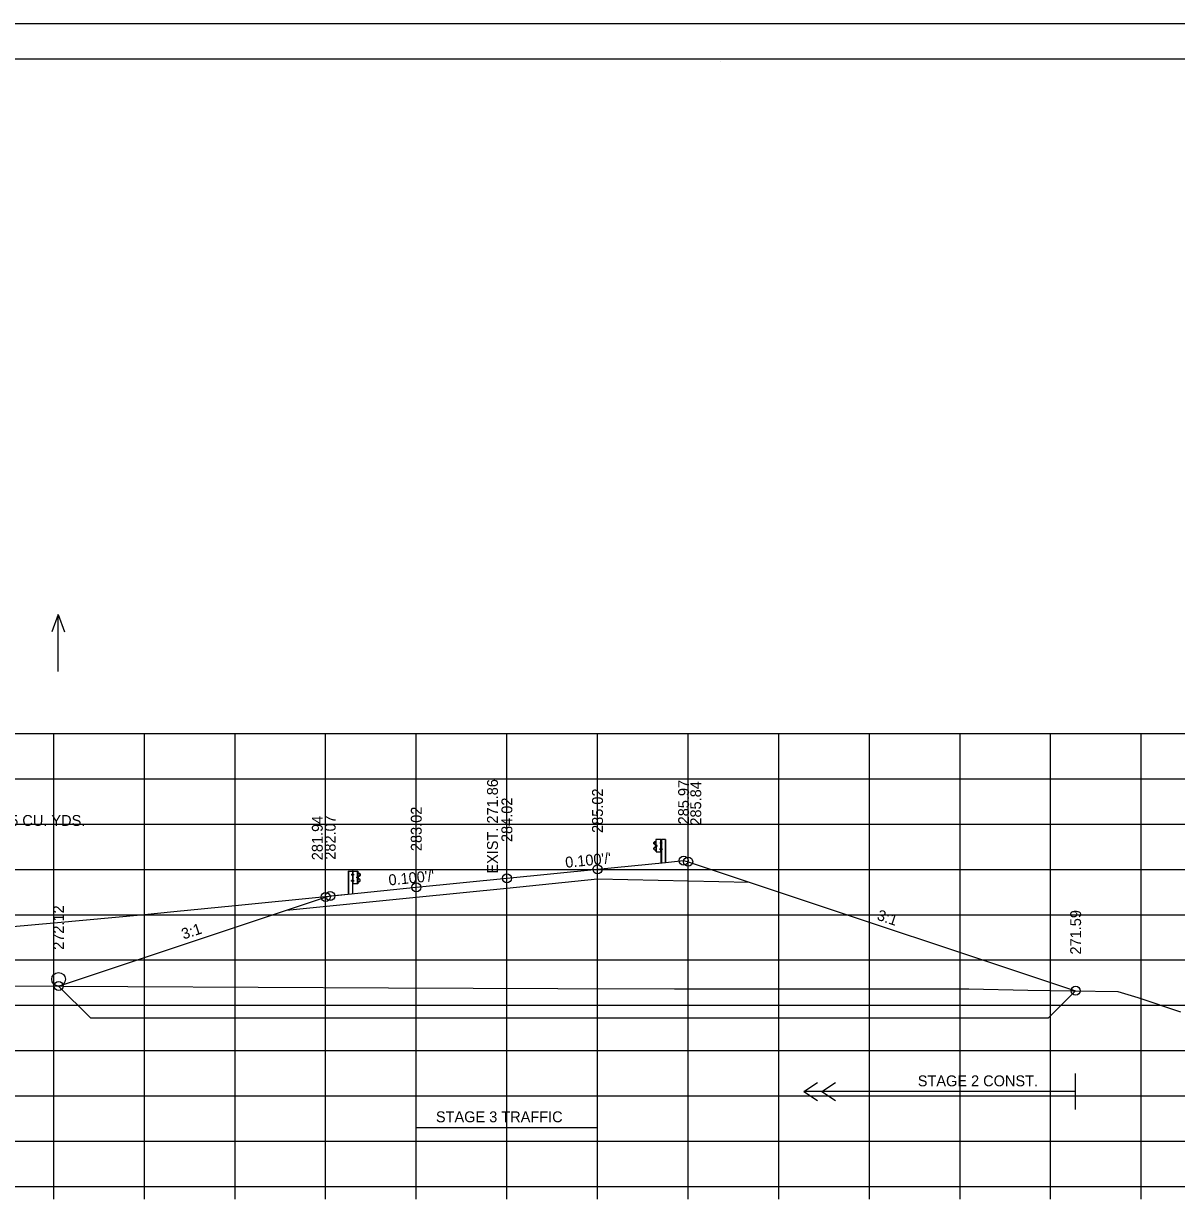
# Model space of a CAD drawing. Extents: x 4667 to 1632277, y -2100 to 724501.
# Drawn here: x 5723.9 to 5851.1, y -387.5 to -257.1 of the extents above; entities that cross this region are included whole.
import ezdxf

# ---------------------------------------------------------------- set-up
doc = ezdxf.new("R2010")
doc.units = 0
for name, color, linetype in [('R_Alt Surface', 7, 'Continuous'), ('R_Axis', 7, 'Continuous'), ('R_Border', 7, 'Continuous'), ('R_Draft', 7, 'Continuous'), ('R_Drive', 7, 'Continuous'), ('R_Exist Surface', 7, 'Continuous'), ('R_Fin Surface', 7, 'Continuous'), ('R_Fin Surface Annot', 7, 'Continuous'), ('R_Grid', 7, 'Continuous'), ('R_No Plot', 7, 'Continuous'), ('R_Proposed CofA', 7, 'Continuous'), ('R_ROW', 7, 'Continuous'), ('R_Temp Easement', 7, 'Continuous'), ('R_Water', 7, 'Continuous'), ('R_Water Annot', 7, 'Continuous')]:
    doc.layers.add(name, color=color, linetype=linetype)

msp = doc.modelspace()

# ---------------------------------------------------------------- linework, layer by layer
at = {"layer": 'R_Alt Surface'}
msp.add_lwpolyline([(5752.86, -354.91), (5767.18, -353.48), (5777.18, -352.48), (5787.18, -351.48), (5803.91, -351.82)], dxfattribs=at)
at = {"layer": 'R_Axis'}
for p, q in [((5667.18, -385.42), (5947.18, -385.42)), ((5727.18, -386.82), (5727.18, -385.42)), ((5737.18, -386.82), (5737.18, -385.42)), ((5747.18, -386.82), (5747.18, -385.42)), ((5757.18, -386.82), (5757.18, -385.42)), ((5767.18, -386.82), (5767.18, -385.42)), ((5777.18, -386.82), (5777.18, -385.42)), ((5787.18, -386.82), (5787.18, -385.42)), ((5797.18, -386.82), (5797.18, -385.42)), ((5807.18, -386.82), (5807.18, -385.42)), ((5817.18, -386.82), (5817.18, -385.42)), ((5827.18, -386.82), (5827.18, -385.42)), ((5837.18, -386.82), (5837.18, -385.42)), ((5847.18, -386.82), (5847.18, -385.42))]:
    msp.add_line(p, q, dxfattribs=at)
at = {"layer": 'R_Border'}
for p, q in [((5648.18, -260.96), (5964.36, -260.96)), ((5800.7, -261.22), (5800.7, -261.22)), ((5800.7, -261.22), (5800.7, -261.22))]:
    msp.add_line(p, q, dxfattribs=at)
at = {"layer": 'R_Draft'}
for p, q in [((5793.51, -348.3), (5793.38, -348.19)), ((5793.39, -347.45), (5793.52, -347.35)), ((5793.56, -347.7), (5793.39, -347.6)), ((5793.4, -347.47), (5793.53, -347.36)), ((5793.57, -347.68), (5793.4, -347.57)), ((5793.52, -348.28), (5793.4, -348.17)), ((5793.41, -348.03), (5793.57, -347.93)), ((5793.42, -348.05), (5793.58, -347.95)), ((5793.52, -347.35), (5793.63, -347.29)), ((5793.63, -348.34), (5793.52, -348.28)), ((5793.53, -347.36), (5793.62, -347.31)), ((5793.6, -347.88), (5793.6, -347.75)), ((5793.62, -347.88), (5793.62, -347.75)), ((5793.66, -348.5), (5793.66, -347.14)), ((5793.67, -347.88), (5793.67, -347.76)), ((5793.67, -347.76), (5793.72, -347.76)), ((5793.67, -347.79), (5793.72, -347.79)), ((5793.67, -347.85), (5793.72, -347.85)), ((5793.67, -347.85), (5793.72, -347.85)), ((5793.67, -347.88), (5793.72, -347.88)), ((5793.73, -347.87), (5793.73, -347.77)), ((5794.15, -347.44), (5794.1, -347.44)), ((5794.1, -347.44), (5794.1, -347.56)), ((5794.1, -347.5), (5794.16, -347.5)), ((5794.15, -347.56), (5794.1, -347.56)), ((5794.1, -348.25), (5794.1, -348.12)), ((5794.1, -348.12), (5794.15, -348.12)), ((5794.1, -348.19), (5794.16, -348.19)), ((5794.1, -348.25), (5794.15, -348.25)), ((5794.16, -347.13), (5794.17, -347.13)), ((5794.16, -347.13), (5794.23, -347.13)), ((5794.19, -349.65), (5794.19, -347.13)), ((5794.23, -347.56), (5794.23, -347.43)), ((5794.23, -347.43), (5794.28, -347.43)), ((5794.23, -347.46), (5794.28, -347.46)), ((5794.23, -347.53), (5794.27, -347.53)), ((5794.23, -347.53), (5794.28, -347.53)), ((5794.23, -347.56), (5794.28, -347.56)), ((5794.24, -348.25), (5794.24, -348.12)), ((5794.24, -348.12), (5794.29, -348.12)), ((5794.24, -348.15), (5794.29, -348.15)), ((5794.24, -348.22), (5794.28, -348.22)), ((5794.24, -348.22), (5794.29, -348.22)), ((5794.24, -348.25), (5794.29, -348.25)), ((5794.28, -347.54), (5794.28, -347.45)), ((5794.29, -348.23), (5794.29, -348.14)), ((5794.65, -347.13), (5794.65, -349.65)), ((5794.68, -347.13), (5794.68, -349.65)), ((5793.62, -348.36), (5793.51, -348.3)), ((5794.16, -348.5), (5794.19, -348.5))]:
    msp.add_line(p, q, dxfattribs=at)
for points in [[(5793.63, -347.13), (5793.64, -348.5), (5794.16, -348.5), (5794.16, -347.13)], [(5793.67, -347.74), (5793.67, -347.9), (5793.66, -347.9), (5793.66, -347.74)], [(5793.73, -347.79), (5793.73, -347.85), (5793.76, -347.85), (5793.76, -347.79)], [(5794.1, -347.44), (5794.1, -347.56), (5794.16, -347.56), (5794.16, -347.44)], [(5794.1, -348.12), (5794.1, -348.25), (5794.16, -348.25), (5794.16, -348.12)], [(5794.23, -347.41), (5794.23, -347.58), (5794.22, -347.58), (5794.22, -347.41)], [(5794.24, -348.1), (5794.24, -348.27), (5794.23, -348.27), (5794.23, -348.1)], [(5794.29, -347.47), (5794.29, -347.53), (5794.31, -347.53), (5794.31, -347.47)], [(5794.3, -348.15), (5794.3, -348.22), (5794.32, -348.22), (5794.32, -348.15)]]:
    msp.add_lwpolyline(points, close=True, dxfattribs=at)
msp.add_lwpolyline([(5794.68, -347.13), (5794.23, -347.13), (5794.23, -349.65)], dxfattribs=at)
for centre, radius, start, end in [((5793.43, -347.52), 0.0856, 122.0217, 240.7501), ((5793.47, -348.13), 0.109, 120.88, 214.7816), ((5793.43, -347.52), 0.062, 122.0217, 240.7501), ((5793.47, -348.13), 0.0854, 120.88, 214.7816), ((5793.53, -347.76), 0.0622, 4.9556, 61.894), ((5793.6, -347.82), 0.0453, 93.9303, 257.0446), ((5793.53, -347.76), 0.0865, 4.9556, 61.894), ((5793.55, -347.89), 0.0462, 293.1464, 8.2196), ((5793.55, -347.89), 0.0703, 293.1464, 8.2196), ((5793.71, -347.77), 0.022, 317.7756, 45.4255), ((5793.64, -347.82), 0.0922, 339.7423, 20.2577), ((5793.7, -347.87), 0.025, 323.3766, 39.0666), ((5794.26, -347.45), 0.022, 317.7756, 45.4255), ((5794.19, -347.5), 0.0922, 339.7423, 20.2577), ((5794.26, -347.54), 0.025, 323.3766, 39.0666), ((5794.27, -348.14), 0.022, 317.7756, 45.4255), ((5794.2, -348.19), 0.0922, 339.7423, 20.2577), ((5794.27, -348.23), 0.025, 323.3766, 39.0666)]:
    msp.add_arc(centre, radius, start, end, dxfattribs=at)
at = {"layer": 'R_Drive'}
msp.add_lwpolyline([(5720.16, -356.95), (5727.18, -356.33), (5737.18, -355.39), (5740.43, -355.07), (5747.18, -354.4), (5757.18, -353.4), (5767.18, -352.4)], dxfattribs=at)
at = {"layer": 'R_Exist Surface'}
msp.add_lwpolyline([(5667.18, -364.47), (5696.52, -363.3), (5708.04, -363.26), (5714.57, -363.26), (5720.94, -363.26), (5764.1, -363.49), (5782.81, -363.58), (5795.66, -363.6), (5828.17, -363.6), (5834.67, -363.74), (5844.59, -363.9), (5846.79, -364.56), (5851.51, -366.13)], dxfattribs=at)
at = {"layer": 'R_Fin Surface'}
msp.add_lwpolyline([(5727.71, -363.3), (5752.86, -354.91), (5757.18, -353.47), (5757.68, -353.35), (5759.68, -353.15), (5767.18, -352.4), (5777.18, -351.4), (5787.18, -350.4), (5794.68, -349.65), (5796.68, -349.45), (5797.18, -349.57), (5803.91, -351.82), (5839.94, -363.82)], dxfattribs=at)
at = {"layer": 'R_Grid'}
for p, q in [((5667.18, -335.42), (5947.18, -335.42)), ((5727.18, -385.42), (5727.18, -335.42)), ((5737.18, -385.42), (5737.18, -335.42)), ((5747.18, -385.42), (5747.18, -335.42)), ((5757.18, -385.42), (5757.18, -335.42)), ((5767.18, -385.42), (5767.18, -335.42)), ((5777.18, -385.42), (5777.18, -335.42)), ((5787.18, -385.42), (5787.18, -335.42)), ((5797.18, -385.42), (5797.18, -335.42)), ((5807.18, -385.42), (5807.18, -335.42)), ((5817.18, -385.42), (5817.18, -335.42)), ((5827.18, -385.42), (5827.18, -335.42)), ((5837.18, -385.42), (5837.18, -335.42)), ((5847.18, -385.42), (5847.18, -335.42)), ((5667.18, -340.42), (5947.18, -340.42)), ((5667.18, -345.42), (5947.18, -345.42)), ((5667.18, -350.42), (5947.18, -350.42)), ((5667.18, -355.42), (5947.18, -355.42)), ((5667.18, -360.42), (5947.18, -360.42)), ((5667.18, -365.42), (5947.18, -365.42)), ((5667.18, -370.42), (5947.18, -370.42)), ((5667.18, -375.42), (5947.18, -375.42)), ((5667.18, -380.42), (5947.18, -380.42)), ((5667.18, -385.42), (5947.18, -385.42))]:
    msp.add_line(p, q, dxfattribs=at)
at = {"layer": 'R_No Plot'}
for p, q in [((5635.78, -257.06), (5969.12, -257.06)), ((5759.68, -350.63), (5759.68, -353.15)), ((5759.71, -350.63), (5759.71, -353.15)), ((5760.21, -350.63), (5760.14, -350.63)), ((5760.18, -353.15), (5760.18, -350.63)), ((5760.21, -350.63), (5760.2, -350.63)), ((5760.71, -352), (5760.71, -350.64)), ((5760.85, -350.85), (5760.74, -350.79)), ((5760.84, -350.86), (5760.75, -350.81)), ((5760.97, -350.97), (5760.84, -350.86)), ((5760.98, -350.95), (5760.85, -350.85)), ((5760.07, -351.73), (5760.07, -351.64)), ((5760.08, -351.04), (5760.08, -350.95)), ((5760.13, -351.62), (5760.08, -351.62)), ((5760.13, -351.65), (5760.08, -351.65)), ((5760.13, -351.72), (5760.08, -351.72)), ((5760.13, -351.75), (5760.08, -351.75)), ((5760.14, -350.93), (5760.09, -350.93)), ((5760.14, -350.96), (5760.09, -350.96)), ((5760.14, -351.03), (5760.09, -351.03)), ((5760.14, -351.06), (5760.09, -351.06)), ((5760.13, -351.72), (5760.09, -351.72)), ((5760.14, -351.03), (5760.1, -351.03)), ((5760.13, -351.75), (5760.13, -351.62)), ((5760.14, -351.06), (5760.14, -350.93)), ((5760.21, -352), (5760.17, -352)), ((5760.26, -351), (5760.21, -351)), ((5760.26, -351.69), (5760.21, -351.69)), ((5760.22, -350.94), (5760.27, -350.94)), ((5760.22, -351.06), (5760.27, -351.06)), ((5760.27, -351.62), (5760.22, -351.62)), ((5760.27, -351.75), (5760.22, -351.75)), ((5760.27, -350.94), (5760.27, -351.06)), ((5760.27, -351.75), (5760.27, -351.62)), ((5760.64, -351.37), (5760.64, -351.27)), ((5760.7, -351.26), (5760.65, -351.26)), ((5760.7, -351.29), (5760.65, -351.29)), ((5760.7, -351.35), (5760.65, -351.35)), ((5760.7, -351.35), (5760.65, -351.35)), ((5760.7, -351.38), (5760.65, -351.38)), ((5760.7, -351.38), (5760.7, -351.26)), ((5760.74, -351.84), (5760.84, -351.78)), ((5760.74, -351.86), (5760.86, -351.8)), ((5760.75, -351.38), (5760.75, -351.25)), ((5760.77, -351.38), (5760.77, -351.25)), ((5760.79, -351.18), (5760.97, -351.07)), ((5760.94, -351.55), (5760.79, -351.45)), ((5760.96, -351.53), (5760.8, -351.43)), ((5760.81, -351.2), (5760.98, -351.1)), ((5760.84, -351.78), (5760.97, -351.67)), ((5760.86, -351.8), (5760.98, -351.69))]:
    msp.add_line(p, q, dxfattribs=at)
for points in [[(5635.78, -257.06), (5969.12, -257.06), (5969.12, -470.4), (5635.78, -470.4)], [(5882.1, -260.96), (5901.72, -260.96), (5901.72, -270.84), (5917.84, -270.84), (5941.04, -270.84), (5941.04, -295.17), (5964.36, -295.17), (5964.36, -466.42), (5648.18, -466.42), (5648.18, -260.96)], [(5760.73, -350.63), (5760.73, -352), (5760.21, -352), (5760.21, -350.63)], [(5760.07, -351.65), (5760.07, -351.72), (5760.05, -351.72), (5760.05, -351.65)], [(5760.08, -350.97), (5760.08, -351.03), (5760.06, -351.03), (5760.06, -350.97)], [(5760.13, -351.6), (5760.13, -351.77), (5760.14, -351.77), (5760.14, -351.6)], [(5760.14, -350.91), (5760.14, -351.08), (5760.15, -351.08), (5760.15, -350.91)], [(5760.26, -350.94), (5760.26, -351.06), (5760.21, -351.06), (5760.21, -350.94)], [(5760.26, -351.62), (5760.26, -351.75), (5760.21, -351.75), (5760.21, -351.62)], [(5760.64, -351.29), (5760.64, -351.35), (5760.61, -351.35), (5760.61, -351.29)], [(5760.69, -351.24), (5760.69, -351.4), (5760.7, -351.4), (5760.7, -351.24)]]:
    msp.add_lwpolyline(points, close=True, dxfattribs=at)
msp.add_lwpolyline([(5759.68, -350.63), (5760.14, -350.63), (5760.14, -353.15)], dxfattribs=at)
for centre in [(5796.68, -349.45), (5797.18, -349.57), (5787.18, -350.4), (5767.18, -352.4), (5777.18, -351.4), (5757.18, -353.47), (5757.68, -353.35), (5727.71, -363.3), (5839.94, -363.82)]:
    msp.add_circle(centre, 0.5, dxfattribs=at)
for centre, radius, start, end in [((5760.1, -351.64), 0.022, 134.5745, 222.2244), ((5760.17, -351.69), 0.0922, 159.7423, 200.2577), ((5760.1, -351.73), 0.025, 140.9334, 216.6234), ((5760.11, -350.95), 0.022, 134.5745, 222.2244), ((5760.18, -351), 0.0922, 159.7423, 200.2577), ((5760.11, -351.04), 0.025, 140.9334, 216.6234), ((5760.66, -351.27), 0.022, 134.5745, 222.2244), ((5760.73, -351.32), 0.0922, 159.7423, 200.2577), ((5760.67, -351.37), 0.025, 140.9334, 216.6234), ((5760.84, -351.26), 0.0865, 118.106, 175.0444), ((5760.82, -351.39), 0.0703, 171.7804, 246.8536), ((5760.84, -351.26), 0.0622, 118.106, 175.0444), ((5760.77, -351.32), 0.0453, 282.9554, 86.0697), ((5760.82, -351.39), 0.0462, 171.7804, 246.8536), ((5760.9, -351.63), 0.0854, 325.2184, 59.12), ((5760.9, -351.63), 0.109, 325.2184, 59.12), ((5760.94, -351.02), 0.062, 299.2499, 57.9783), ((5760.94, -351.02), 0.0856, 299.2499, 57.9783)]:
    msp.add_arc(centre, radius, start, end, dxfattribs=at)
at = {"layer": 'R_Proposed CofA'}
for p, q in [((5809.94, -374.94), (5811.44, -373.94)), ((5811.94, -374.94), (5813.44, -373.94)), ((5809.94, -374.94), (5811.44, -375.94)), ((5811.94, -374.94), (5813.44, -375.94))]:
    msp.add_line(p, q, dxfattribs=at)
at = {"layer": 'R_ROW'}
for p, q in [((5727.71, -363.3), (5731.24, -366.82)), ((5839.94, -363.82), (5836.94, -366.82)), ((5731.24, -366.82), (5836.94, -366.82))]:
    msp.add_line(p, q, dxfattribs=at)
at = {"layer": 'R_Temp Easement'}
for p, q in [((5839.94, -376.94), (5839.94, -372.94)), ((5839.94, -374.94), (5809.94, -374.94)), ((5767.18, -380.94), (5767.18, -376.94)), ((5787.18, -380.94), (5787.18, -376.94)), ((5787.18, -378.94), (5767.18, -378.94))]:
    msp.add_line(p, q, dxfattribs=at)
at = {"layer": 'R_Water'}
msp.add_circle((5727.71, -362.55), 0.75, dxfattribs=at)
at = {"layer": 'R_Water Annot'}
for p, q in [((5727.66, -322.27), (5726.96, -324.2)), ((5727.66, -328.56), (5727.66, -322.27)), ((5727.66, -322.27), (5728.36, -324.2))]:
    msp.add_line(p, q, dxfattribs=at)

# ---------------------------------------------------------------- texts
at = {"layer": 'R_Fin Surface Annot'}
for s, rotation, p in [('285.02', 90, (5787.78, -346.4)), ('285.97', 90, (5797.28, -345.45)), ('285.84', 90, (5798.62, -345.59)), ('284.02', 90, (5777.78, -347.4)), ('283.02', 90, (5767.78, -348.4)), ('281.94', 90, (5756.86, -349.41)), ('282.07', 90, (5758.28, -349.35)), ("0.100'/'", 5.7106, (5783.68, -350.25)), ("0.100'/'", 5.7106, (5764.18, -352.2)), ('272.12', 90, (5728.31, -359.3)), ('3:1', 341.5651, (5817.93, -355.96)), ('271.59', 90, (5840.54, -359.82)), ('3:1', 18.4349, (5741.5, -358.17))]:
    msp.add_text(s, height=1.2, rotation=rotation, dxfattribs=at).set_placement(p)
at = {"layer": 'R_Temp Easement'}
msp.add_text('EXIST. 271.86', height=1.2, rotation=90, dxfattribs=at).set_placement((5776.19, -350.89))
for s, p in [('STAGE 2 CONST.', (5822.52, -374.36)), ('STAGE 3 TRAFFIC', (5769.35, -378.33))]:
    msp.add_text(s, height=1.1985, dxfattribs=at).set_placement(p)
at = {"layer": 'R_Water Annot'}
msp.add_text('UNCLASSIFIED EXCAVATION = 15 CU. YDS.', height=1.2, dxfattribs=at).set_placement((5697.18, -345.62))

doc.saveas('drawing.dxf')
